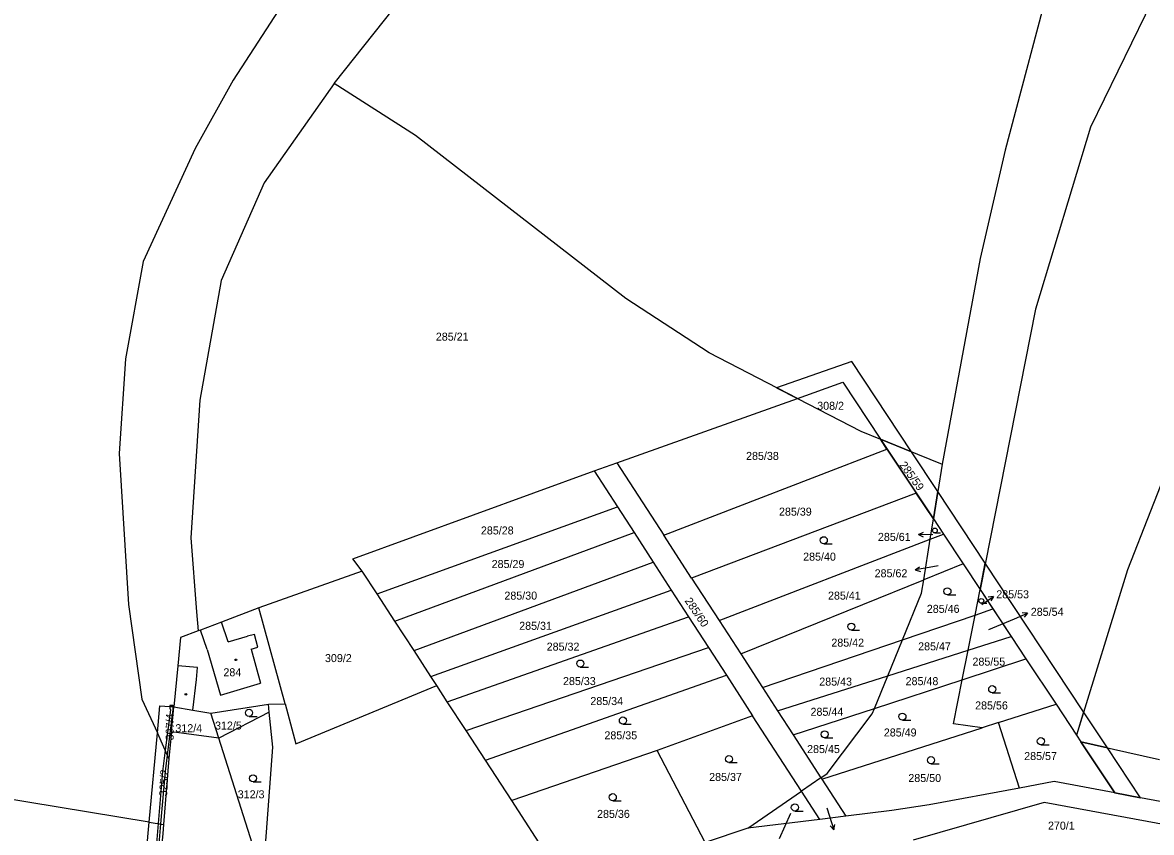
# Model space of a CAD drawing. Extents: x -758582 to -751794, y -998770 to -994350.
# Drawn here: x -755427.1 to -755187.4, y -995107.1 to -994935.2 of the extents above; entities that cross this region are included whole.
import ezdxf

# ---------------------------------------------------------------- set-up
doc = ezdxf.new("R2010")
doc.units = 0
for name, color, linetype in [('Hranice parcel', 7, 'Continuous'), ('Parcelní čísla', 7, 'Continuous'), ('Pop  PČ popisy', 7, 'Continuous'), ('Vnitřní kresba', 7, 'Continuous'), ('Věcná břemena k části', 7, 'Continuous'), ('Značky budov', 7, 'Continuous'), ('Značky kultur', 7, 'Continuous')]:
    doc.layers.add(name, color=color, linetype=linetype)

msp = doc.modelspace()

# ---------------------------------------------------------------- linework, layer by layer
at = {"layer": 'Hranice parcel'}
for p, q in [((-755211.97, -994996.06), (-755223.74, -995055.54)), ((-755262.54, -995014.99), (-755281.26, -995005.29)), ((-755300.86, -995028.64), (-755262.54, -995014.99)), ((-755243.57, -995025.76), (-755244.86, -995023.66)), ((-755244.86, -995023.66), (-755231.81, -995028.92)), ((-755290.89, -995044.03), (-755243.57, -995025.76)), ((-755243.57, -995025.76), (-755237.3, -995035.07)), ((-755305.71, -995030.36), (-755300.86, -995028.64)), ((-755300.86, -995028.64), (-755290.89, -995044.03)), ((-755231.81, -995028.92), (-755233.67, -995040.56)), ((-755305.71, -995030.36), (-755300.76, -995037.99)), ((-755237.3, -995035.07), (-755285, -995053.13)), ((-755233.67, -995040.56), (-755237.3, -995035.07)), ((-755351.8, -995056.45), (-755300.76, -995037.99)), ((-755300.76, -995037.99), (-755297.22, -995043.46)), ((-755234.35, -995044.85), (-755233.67, -995040.56)), ((-755233.67, -995040.56), (-755231.54, -995043.76)), ((-755348.03, -995062.23), (-755297.22, -995043.46)), ((-755297.22, -995043.46), (-755293.15, -995049.75)), ((-755234.35, -995044.85), (-755231.54, -995043.76)), ((-755231.54, -995043.76), (-755227.36, -995050.08)), ((-755285, -995053.13), (-755290.89, -995044.03)), ((-755279.18, -995062.12), (-755234.35, -995044.85)), ((-755235.72, -995053.47), (-755234.35, -995044.85)), ((-755343.95, -995068.5), (-755293.15, -995049.75)), ((-755293.15, -995049.75), (-755289.32, -995055.66)), ((-755227.36, -995050.08), (-755235.72, -995053.47)), ((-755227.36, -995050.08), (-755223.74, -995055.54)), ((-755354.94, -995051.62), (-755376.88, -995059.45)), ((-755351.8, -995056.45), (-755354.94, -995051.62)), ((-755285, -995053.13), (-755279.18, -995062.12)), ((-755274.57, -995069.22), (-755235.72, -995053.47)), ((-755192.41, -995051.37), (-755203.29, -995086.42)), ((-755340.38, -995073.98), (-755289.32, -995055.66)), ((-755289.32, -995055.66), (-755285.63, -995061.35)), ((-755224.82, -995060.96), (-755223.74, -995055.54)), ((-755223.74, -995055.54), (-755221.01, -995059.67)), ((-755348.03, -995062.23), (-755351.8, -995056.45)), ((-755376.88, -995059.45), (-755384.84, -995062.45)), ((-755371.33, -995079.81), (-755376.88, -995059.45)), ((-755224.82, -995060.96), (-755221.01, -995059.67)), ((-755221.01, -995059.67), (-755217.14, -995065.51)), ((-755384.84, -995062.45), (-755389.26, -995064.13)), ((-755343.95, -995068.5), (-755348.03, -995062.23)), ((-755336.88, -995079.35), (-755285.63, -995061.35)), ((-755285.63, -995061.35), (-755281.42, -995067.85)), ((-755279.18, -995062.12), (-755274.57, -995069.22)), ((-755240.23, -995066.21), (-755224.82, -995060.96)), ((-755226.3, -995068.43), (-755224.82, -995060.96)), ((-755389.26, -995064.13), (-755389.78, -995064.32)), ((-755226.3, -995068.43), (-755217.14, -995065.51)), ((-755217.14, -995065.51), (-755214.02, -995070.26)), ((-755332.89, -995085.48), (-755281.42, -995067.85)), ((-755281.42, -995067.85), (-755277.62, -995073.72)), ((-755269.97, -995076.33), (-755240.23, -995066.21)), ((-755243.37, -995073.87), (-755240.23, -995066.21)), ((-755340.38, -995073.98), (-755343.95, -995068.5)), ((-755274.57, -995069.22), (-755269.97, -995076.33)), ((-755243.37, -995073.87), (-755226.3, -995068.43)), ((-755227.53, -995074.68), (-755226.3, -995068.43)), ((-755227.53, -995074.68), (-755214.02, -995070.26)), ((-755214.02, -995070.26), (-755207.62, -995079.89)), ((-755339.14, -995075.88), (-755340.38, -995073.98)), ((-755328.8, -995091.76), (-755277.62, -995073.72)), ((-755277.62, -995073.72), (-755272.04, -995082.33)), ((-755266.74, -995081.32), (-755243.37, -995073.87)), ((-755246.2, -995080.78), (-755243.37, -995073.87)), ((-755246.2, -995080.78), (-755227.53, -995074.68)), ((-755336.88, -995079.35), (-755339.14, -995075.88)), ((-755269.97, -995076.33), (-755266.74, -995081.32)), ((-755374.89, -995079.9), (-755371.33, -995079.81)), ((-755332.89, -995085.48), (-755336.88, -995079.35)), ((-755219.85, -995083.79), (-755207.62, -995079.89)), ((-755207.62, -995079.89), (-755203.29, -995086.42)), ((-755395.46, -995085.73), (-755394.95, -995080.47)), ((-755387.11, -995081.79), (-755374.89, -995079.9)), ((-755385.42, -995087.06), (-755387.11, -995081.79)), ((-755374.72, -995081.56), (-755385.42, -995087.06)), ((-755374.72, -995081.56), (-755374.89, -995079.9)), ((-755266.74, -995081.32), (-755263.44, -995086.41)), ((-755263.44, -995086.41), (-755246.2, -995080.78)), ((-755256.24, -995094.62), (-755246.68, -995081.94)), ((-755246.68, -995081.94), (-755246.2, -995080.78)), ((-755272.04, -995082.33), (-755292.32, -995089.69)), ((-755261.66, -995098.35), (-755272.04, -995082.33)), ((-755219.85, -995083.79), (-755223.31, -995084.89)), ((-755215.37, -995097.67), (-755219.85, -995083.79)), ((-755400.18, -995104.9), (-755398.46, -995085.98)), ((-755396, -995091.4), (-755398.46, -995085.98)), ((-755395.46, -995085.73), (-755396, -995091.4)), ((-755385.42, -995087.06), (-755395.46, -995085.73)), ((-755376, -995116.54), (-755385.42, -995087.06)), ((-755328.8, -995091.76), (-755332.89, -995085.48)), ((-755263.44, -995086.41), (-755257.54, -995095.51)), ((-755257.38, -995095.76), (-755223.31, -995084.89)), ((-755203.29, -995086.42), (-755202.33, -995087.87)), ((-755202.33, -995087.87), (-755185.61, -995091.58)), ((-755195.16, -995098.7), (-755202.33, -995087.87)), ((-755400.18, -995104.9), (-755484.59, -995091.06)), ((-755396, -995091.4), (-755397.16, -995105.39)), ((-755323.21, -995100.33), (-755328.8, -995091.76)), ((-755292.32, -995089.69), (-755323.21, -995100.33)), ((-755282.14, -995109.23), (-755292.32, -995089.69)), ((-755257.54, -995095.51), (-755261.66, -995098.35)), ((-755257.54, -995095.51), (-755256.24, -995094.62)), ((-755257.54, -995095.51), (-755257.38, -995095.76)), ((-755257.38, -995095.76), (-755252.27, -995103.65)), ((-755273.1, -995106.22), (-755261.66, -995098.35)), ((-755257.78, -995104.33), (-755261.66, -995098.35)), ((-755313.93, -995114.57), (-755323.21, -995100.33)), ((-755252.27, -995103.65), (-755257.78, -995104.33)), ((-755400.18, -995104.9), (-755397.16, -995105.39)), ((-755273.1, -995106.22), (-755282.14, -995109.23)), ((-755257.78, -995104.33), (-755273.1, -995106.22))]:
    msp.add_line(p, q, dxfattribs=at)
for points in [[(-755360.92, -994948.15), (-755339.8, -994921.56), (-755316.43, -994893.06), (-755284.43, -994856.14), (-755243.23, -994814.9), (-755217.8, -994796.33), (-755198.26, -994789.83), (-755181.91, -994790.43), (-755163.48, -994797.88)], [(-755163.48, -994797.88), (-755136.89, -994816.34), (-755136.62, -994831.98), (-755138.02, -994836.23), (-755149.14, -994848.27), (-755179.9, -994881.05), (-755197.99, -994903.36), (-755208.12, -994923.56), (-755218.42, -994962.29), (-755223.75, -994985.27), (-755231.81, -995028.92)], [(-755078.5, -994834.42), (-755089.22, -994854.99), (-755124.1, -994912.57), (-755146.36, -994948.38), (-755172.93, -995001.52), (-755192.41, -995051.37)], [(-755117.99, -994840.06), (-755174.16, -994903.88), (-755200.33, -994957.38), (-755211.97, -994996.06)], [(-755334.71, -994867.17), (-755343.13, -994889.43), (-755353.56, -994903.02), (-755382.36, -994947.45), (-755390.45, -994961.94), (-755401.45, -994985.89), (-755405.25, -995006.61), (-755406.54, -995026.68), (-755404.6, -995058.72), (-755401.73, -995078.79), (-755398.46, -995085.98)], [(-755360.92, -994948.15), (-755375.8, -994969.24), (-755384.94, -994989.97), (-755389.41, -995015.38), (-755391.32, -995044.56), (-755390.14, -995060.29), (-755389.78, -995064.32)], [(-755281.26, -995005.29), (-755298.98, -994993.8), (-755343.63, -994959.16), (-755360.92, -994948.15)], [(-755262.54, -995014.99), (-755252.87, -995011.54), (-755244.86, -995023.66)], [(-755262.54, -995014.99), (-755249.07, -995021.96), (-755244.86, -995023.66)], [(-755354.94, -995051.62), (-755356.96, -995049.02), (-755305.71, -995030.36)], [(-755240.23, -995066.21), (-755236.18, -995056.33), (-755235.72, -995053.47)], [(-755389.78, -995064.32), (-755393.57, -995065.75), (-755394.13, -995071.72), (-755394.95, -995080.47)], [(-755223.31, -995084.89), (-755229.39, -995084.06), (-755227.53, -995074.68)], [(-755371.33, -995079.81), (-755369.02, -995088.28), (-755339.14, -995075.88)], [(-755398.46, -995085.98), (-755397.94, -995080.19), (-755395.8, -995080.39), (-755395.09, -995080.46), (-755394.95, -995080.47)], [(-755394.95, -995080.47), (-755390.94, -995081.14), (-755387.11, -995081.79)], [(-755376, -995116.54), (-755373.96, -995088.98), (-755374.72, -995081.56)], [(-755195.16, -995098.7), (-755207.98, -995096.29), (-755215.37, -995097.67)], [(-755215.37, -995097.67), (-755234.57, -995101.25), (-755242.52, -995102.45), (-755252.27, -995103.65)], [(-755135.57, -995107.01), (-755166.92, -995104.01), (-755189.68, -995099.73), (-755195.16, -995098.7)], [(-755169.07, -995108.29), (-755210.16, -995100.72), (-755237.97, -995108.77)], [(-755406.77, -995146.2), (-755403.11, -995137.2), (-755400.18, -995104.9)], [(-755397.16, -995105.39), (-755397.32, -995107.31), (-755400.19, -995138)]]:
    msp.add_lwpolyline(points, dxfattribs=at)
at = {"layer": 'Pop  PČ popisy'}
for p, q in [((-755236.79, -995043.85), (-755235.77, -995043.39)), ((-755233.79, -995043.96), (-755236.79, -995043.85)), ((-755236.79, -995043.85), (-755235.81, -995044.39)), ((-755237.51, -995051.39), (-755236.61, -995050.72)), ((-755234.55, -995050.87), (-755237.51, -995051.39)), ((-755232.65, -995050.53), (-755234.55, -995050.87)), ((-755237.51, -995051.39), (-755236.43, -995051.71)), ((-755223.37, -995058.71), (-755220.91, -995056.99)), ((-755220.91, -995056.99), (-755222.02, -995057.15)), ((-755220.91, -995056.99), (-755221.45, -995057.97)), ((-755216.44, -995061.73), (-755213.68, -995060.56)), ((-755213.68, -995060.56), (-755214.8, -995060.49)), ((-755213.68, -995060.56), (-755214.4, -995061.41)), ((-755221.87, -995064.02), (-755216.44, -995061.73)), ((-755264.01, -995103.05), (-755265.21, -995105.74)), ((-755256.28, -995101.89), (-755255.7, -995103.66)), ((-755255.7, -995103.66), (-755254.77, -995106.51)), ((-755265.21, -995105.74), (-755266.43, -995108.48)), ((-755254.77, -995106.51), (-755255.56, -995105.72)), ((-755254.77, -995106.51), (-755254.61, -995105.41))]:
    msp.add_line(p, q, dxfattribs=at)
at = {"layer": 'Vnitřní kresba'}
for p, q in [((-755383.41, -995066.67), (-755384.84, -995062.45)), ((-755387.89, -995068.27), (-755389.26, -995064.13)), ((-755383.41, -995066.67), (-755379.34, -995065.45)), ((-755377.84, -995065.05), (-755379.34, -995065.45)), ((-755377.09, -995067.76), (-755377.84, -995065.05)), ((-755378.57, -995068.18), (-755377.09, -995067.76)), ((-755387.89, -995068.27), (-755385.02, -995077.97)), ((-755378.57, -995068.18), (-755376.53, -995075.42)), ((-755389.9, -995072.12), (-755394.13, -995071.72)), ((-755390.14, -995074.65), (-755389.9, -995072.12)), ((-755390.94, -995081.14), (-755390.14, -995074.65)), ((-755385.02, -995077.97), (-755376.53, -995075.42))]:
    msp.add_line(p, q, dxfattribs=at)
at = {"layer": 'Věcná břemena k části'}
for points in [[(-755250.98, -995007.17), (-755266.96, -995012.7), (-755262.54, -995014.99), (-755252.87, -995011.54), (-755244.86, -995023.66), (-755238.31, -995026.3)], [(-755238.31, -995026.3), (-755244.86, -995023.66), (-755237.3, -995035.07), (-755233.67, -995040.56), (-755232.73, -995034.72)], [(-755238.31, -995026.3), (-755244.86, -995023.66), (-755233.67, -995040.56), (-755232.73, -995034.72)], [(-755232.73, -995034.72), (-755233.67, -995040.56), (-755231.54, -995043.76), (-755227.36, -995050.08), (-755223.74, -995055.54), (-755222.64, -995049.96)], [(-755232.73, -995034.72), (-755233.67, -995040.56), (-755231.54, -995043.76), (-755227.36, -995050.08), (-755223.74, -995055.54), (-755222.64, -995049.96)], [(-755222.64, -995049.96), (-755223.74, -995055.54), (-755221.01, -995059.67), (-755217.14, -995065.51), (-755214.02, -995070.26), (-755207.62, -995079.89), (-755203.29, -995086.42), (-755202.33, -995087.87), (-755196.71, -995089.12), (-755201.76, -995081.49)], [(-755222.64, -995049.96), (-755223.74, -995055.54), (-755217.14, -995065.51), (-755214.02, -995070.26), (-755207.62, -995079.89), (-755203.29, -995086.42), (-755202.33, -995087.87), (-755196.71, -995089.12), (-755201.76, -995081.49)], [(-755222.64, -995049.96), (-755223.74, -995055.54), (-755221.01, -995059.67), (-755217.14, -995065.51), (-755214.02, -995070.26), (-755207.62, -995079.89), (-755203.29, -995086.42), (-755202.33, -995087.87), (-755196.71, -995089.12), (-755201.76, -995081.49)], [(-755395.8, -995080.39), (-755395.82, -995080.72), (-755395.7, -995081.09), (-755396.79, -995089.66), (-755397.36, -995094.13), (-755398.29, -995105.21), (-755400.13, -995127.25), (-755401.72, -995140.19), (-755403.95, -995143.76), (-755404.25, -995143.81), (-755405.6, -995143.32), (-755405.83, -995143.88), (-755404.31, -995144.43), (-755403.59, -995144.3), (-755401.18, -995140.38), (-755399.53, -995127.31), (-755397.69, -995105.3), (-755396.76, -995094.19), (-755396.32, -995090.7), (-755395.08, -995081.03), (-755395.09, -995080.61), (-755395.09, -995080.46)], [(-755395.78, -995080.12), (-755395.8, -995080.39), (-755395.09, -995080.46), (-755395.09, -995080.12)], [(-755201.76, -995081.49), (-755203.29, -995086.42), (-755202.33, -995087.87), (-755196.71, -995089.12)], [(-755196.71, -995089.12), (-755202.33, -995087.87), (-755195.16, -995098.7), (-755189.68, -995099.73)], [(-755196.71, -995089.12), (-755202.33, -995087.87), (-755195.16, -995098.7), (-755189.68, -995099.73)], [(-755196.71, -995089.12), (-755202.33, -995087.87), (-755195.16, -995098.7), (-755189.68, -995099.73)]]:
    msp.add_lwpolyline(points, close=True, dxfattribs=at)
at = {"layer": 'Značky budov'}
for centre in [(-755381.78, -995070.46), (-755392.4, -995077.79)]:
    msp.add_circle(centre, 0.175, dxfattribs=at)
at = {"layer": 'Značky kultur'}
for p, q in [((-755233.33, -995043.51), (-755232.16, -995043.51)), ((-755256.94, -995045.82), (-755255.19, -995045.82)), ((-755230.68, -995056.67), (-755228.93, -995056.67)), ((-755223.47, -995058.45), (-755222.3, -995058.45)), ((-755251.08, -995064.16), (-755249.33, -995064.16)), ((-755308.64, -995072), (-755306.89, -995072)), ((-755221.17, -995077.44), (-755219.42, -995077.44)), ((-755378.99, -995082.46), (-755377.24, -995082.46)), ((-755299.6, -995084.09), (-755297.85, -995084.09)), ((-755240.23, -995083.26), (-755238.48, -995083.26)), ((-755256.76, -995087.02), (-755255.01, -995087.02)), ((-755210.84, -995088.48), (-755209.09, -995088.48)), ((-755277.08, -995092.27), (-755275.33, -995092.27)), ((-755234.17, -995092.5), (-755232.42, -995092.5)), ((-755378.14, -995096.36), (-755376.39, -995096.36)), ((-755301.74, -995100.36), (-755299.99, -995100.36)), ((-755263.08, -995102.55), (-755261.33, -995102.55))]:
    msp.add_line(p, q, dxfattribs=at)
for centre, radius in [((-755233.34, -995043.01), 0.502), ((-755256.94, -995045.07), 0.75), ((-755230.68, -995055.92), 0.75), ((-755223.48, -995057.95), 0.502), ((-755251.08, -995063.41), 0.75), ((-755308.64, -995071.25), 0.75), ((-755221.17, -995076.69), 0.75), ((-755378.99, -995081.71), 0.75), ((-755240.23, -995082.51), 0.75), ((-755299.6, -995083.34), 0.75), ((-755256.76, -995086.27), 0.75), ((-755210.84, -995087.73), 0.75), ((-755277.08, -995091.52), 0.75), ((-755234.17, -995091.75), 0.75), ((-755378.14, -995095.61), 0.75), ((-755301.74, -995099.61), 0.75), ((-755263.08, -995101.8), 0.75)]:
    msp.add_circle(centre, radius, dxfattribs=at)

# ---------------------------------------------------------------- texts
at = {"layer": 'Parcelní čísla'}
for s, p in [('285/21', (-755339.32, -995002.72)), ('308/2', (-755258.33, -995017.39)), ('285/38', (-755273.44, -995028.03)), ('285/39', (-755266.45, -995039.86)), ('285/28', (-755329.75, -995043.85)), ('285/61', (-755245.44, -995045.22)), ('285/40', (-755261.32, -995049.41)), ('285/29', (-755327.47, -995050.98)), ('285/62', (-755246.14, -995052.94)), ('285/30', (-755324.76, -995057.68)), ('285/41', (-755256.04, -995057.68)), ('285/53', (-755220.31, -995057.4)), ('285/46', (-755235.06, -995060.49)), ('285/54', (-755212.98, -995061.12)), ('285/31', (-755321.62, -995064.09)), ('285/32', (-755315.78, -995068.51)), ('285/42', (-755255.33, -995067.66)), ('285/47', (-755236.9, -995068.45)), ('309/2', (-755362.86, -995070.94)), ('285/55', (-755225.36, -995071.69)), ('284', (-755384.43, -995073.95)), ('285/33', (-755312.32, -995075.82)), ('285/43', (-755257.9, -995075.93)), ('285/48', (-755239.56, -995075.84)), ('285/34', (-755306.51, -995080.06)), ('285/56', (-755224.8, -995080.99)), ('285/44', (-755259.75, -995082.34)), ('312/4', (-755394.63, -995085.82)), ('312/5', (-755386.21, -995085.26)), ('285/35', (-755303.52, -995087.33)), ('285/49', (-755244.19, -995086.73)), ('285/45', (-755260.48, -995090.25)), ('285/57', (-755214.38, -995091.73)), ('285/37', (-755281.28, -995096.17)), ('285/50', (-755238.98, -995096.39)), ('312/3', (-755381.39, -995099.85)), ('285/36', (-755305.08, -995104.01)), ('270/1', (-755209.33, -995106.5))]:
    msp.add_text(s, height=1.7, dxfattribs=at).set_placement(p)
for s, rotation, p in [('285/59', 306, (-755240.96, -995029.11)), ('285/60', 304, (-755286.55, -995057.94)), ('307/4', 89, (-755395.01, -995087.56)), ('325/2', 87, (-755396.39, -995099.46))]:
    msp.add_text(s, height=1.7, rotation=rotation, dxfattribs=at).set_placement(p)

doc.saveas('drawing.dxf')
